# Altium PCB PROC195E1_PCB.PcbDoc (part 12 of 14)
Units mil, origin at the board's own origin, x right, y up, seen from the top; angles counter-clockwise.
Board outline 3110.24 x 2500 mil, 10 copper layers (Top Layer, L02_GND1, L03_SIG1, L04_GND2, L05_PWR1, L06_PWR2, L07_GND3, L08_SIG2, L09_GND4, Bottom Layer), stack 66.407 mil thick; 571 components, 538 nets, 6726 pads, 1286 vias.
Unrouted connection lines stored in the file: 4.
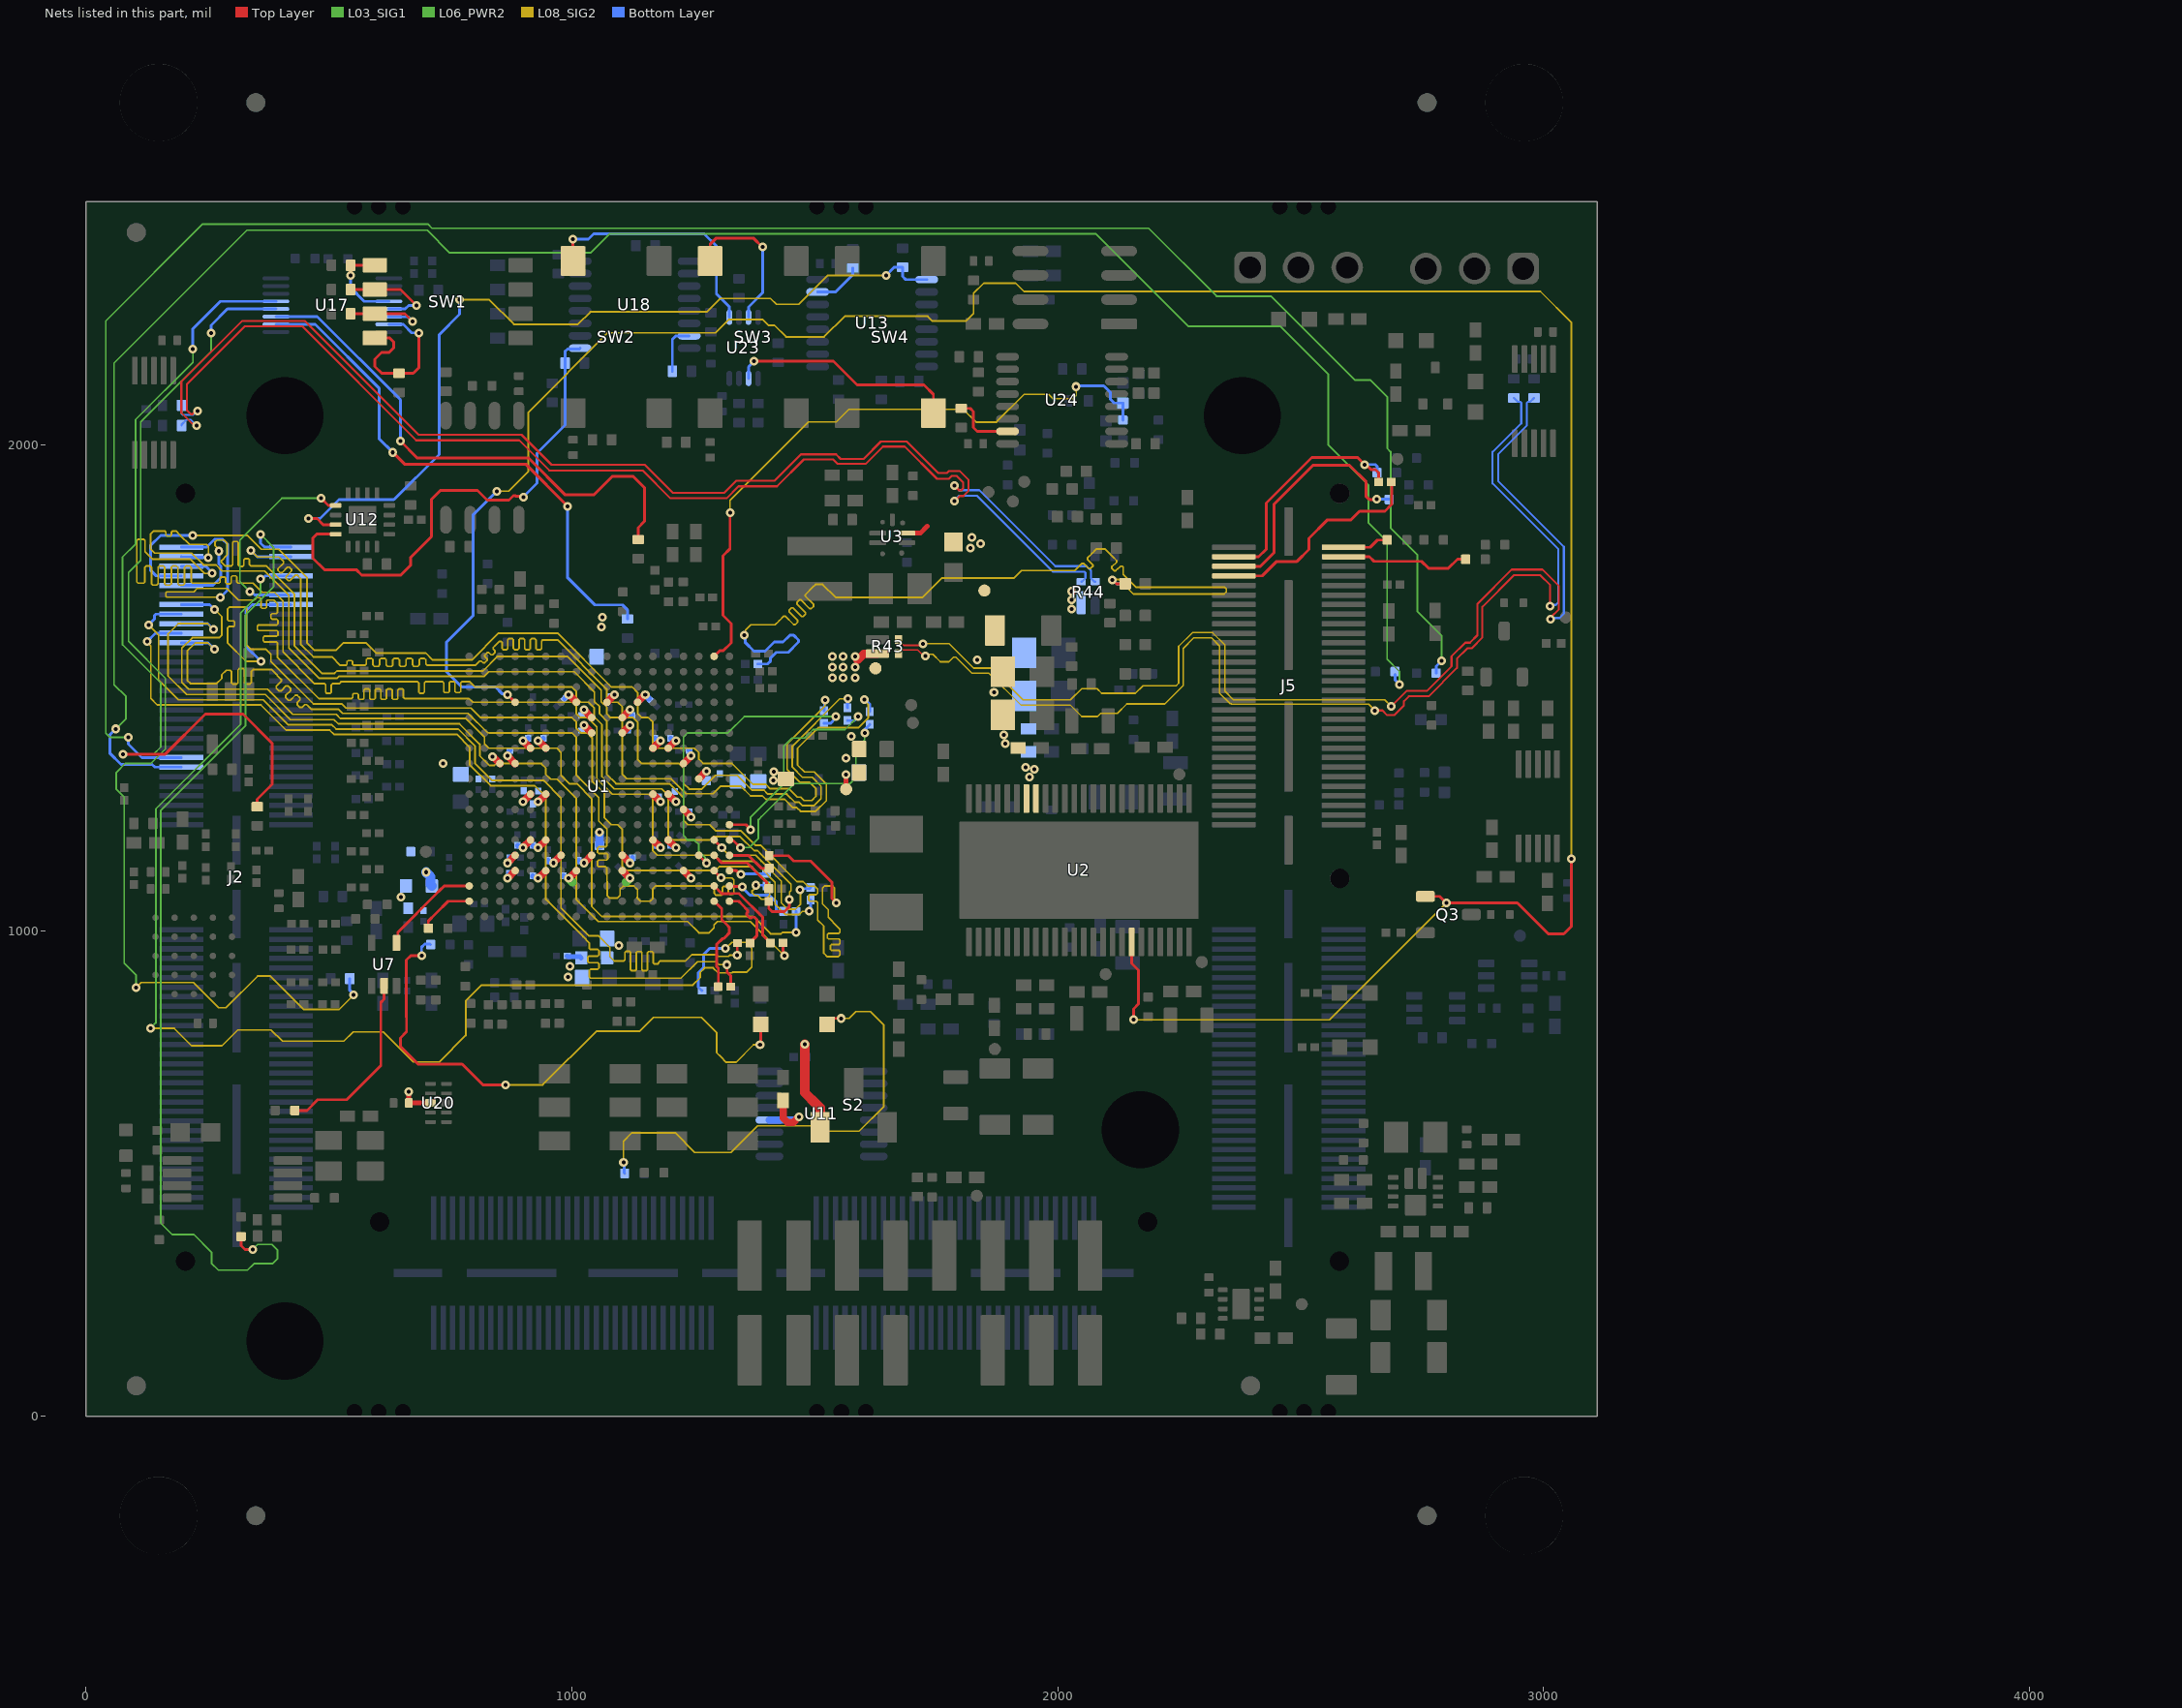
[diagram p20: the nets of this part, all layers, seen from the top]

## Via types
v1: diameter 18, hole 8, Top Layer to Bottom Layer, tented both sides, 1226 vias
v2: diameter 19.68, hole 7.87, Top Layer to Bottom Layer, tented top, 54 vias
v3: diameter 19.68, hole 7.87, Top Layer to Bottom Layer, 4 vias
v4: diameter 19.68, hole 7.87, Top Layer to Bottom Layer, tented both sides, 2 vias

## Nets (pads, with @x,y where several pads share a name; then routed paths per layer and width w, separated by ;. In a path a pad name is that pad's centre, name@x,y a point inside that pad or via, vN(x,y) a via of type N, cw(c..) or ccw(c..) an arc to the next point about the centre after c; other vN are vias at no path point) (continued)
R_PR0_PRU1_GPIO15: R91.2 R170.2 U1.A17 | length 1356.7
  Top Layer w5.66: 1311.87,1575.88 1328.05,1592.05
  Top Layer w5.8: U1.A17@1293.1,1564.41 1304.57,1575.88 1311.87,1575.88 ; v1(1325.82,1860.38) 1325.82,1786.1 1311.32,1771.6 1311.32,1649.01 1328.05,1632.27 1328.05,1629.65 1328.05,1592.05
  L08_SIG2 w3.6: v1(1325.82,1860.38) 1325.82,1885.82 1486.9,2046.9 1544.45,2046.9 1570.37,2072.82 1805.61,2072.82 1831.8,2046.63 1874.14,2046.63 1931.15,2103.63 1981.6,2103.63 1990.34,2094.89 2031.43,2094.89 2038.1,2101.55 v1(2038.1,2119.74)
  Bottom Layer w5.8: v1(2038.1,2119.74) 2039.76,2121.41 2094.91,2121.41 2108.52,2107.79 2108.52,2093.83 2116.52,2085.84 R91.2@2134.23,2085.84 R170.2@2134.23,2050.7
R_PR0_PRU1_GPIO16: R90.2 R145.1 R171.2 | length 1936.7
  Top Layer w5.8: v1(2112.5,1722.11) 2113.35,1722.11 2121.54,1713.93 R90.2@2139.12,1713.93
  L08_SIG2 w3.6: v1(1355.2,1608.12) 1357.8,1610.73 1357.8,1618.68 1368.48,1629.36 1390.29,1629.36 1418.57,1629.36 1426.89,1637.67 1436.36,1647.15 1439.64,1647.15 1456.76,1630.03 1460.04,1630.03 1464.96,1634.96 1464.96,1638.24 1447.21,1655.99 1447.21,1659.27 1452.13,1664.19 1455.41,1664.19 1473.16,1646.44 1476.44,1646.44 1481.37,1651.36 1481.37,1654.64 1463.61,1672.4 1463.61,1675.68 1468.53,1680.6 1471.81,1680.6 1489.57,1662.84 1492.85,1662.84 1497.77,1667.77 1497.77,1671.05 1480.65,1688.16 1480.65,1691.44 1496.11,1706.9 1501.74,1712.53 1516.47,1712.53 1543,1686 1722.14,1686 1761.9,1725.76 1910.79,1725.76 1926.02,1740.99 2035.21,1740.99 2040.54,1746.33 2050.02,1755.8 2053.3,1755.8 2064.16,1744.94 2067.44,1744.94 2072.36,1749.86 2072.36,1753.14 2061.5,1764.01 2061.5,1767.29 2070.61,1776.39 2079.43,1785.22 2097.78,1785.22 2112.01,1770.99 2113.28,1769.72 2121.49,1761.51 2121.34,1758.23 2111.55,1749.32 2111.39,1746.04 2116.08,1740.89 2119.35,1740.74 2129.71,1750.17 2132.99,1750.01 2135,1748 2135,1743.96 2135,1733.06 2141.51,1726.55 2161.06,1707 2343,1707 2347,1703 2347,1697.15 2342.62,1692.77 2156.14,1692.77 2126.54,1722.38 2112.77,1722.38 v1(2112.5,1722.11)
  Bottom Layer w5.8: v1(1355.2,1608.12) 1357.49,1605.83 1357.49,1592.48 1375,1574.97 1390.29,1574.97 1397.97,1574.97 1417,1594 1435.07,1594 1448.8,1607.74 1457.11,1607.74 1466.86,1597.98 1466.86,1593.92 1445.57,1572.63 1420.69,1572.63 1409.32,1561.26 1409.32,1554.91 1403.11,1548.7 1390.29,1548.7 R145.1@1383.21,1548.7 ; v1(2112.5,1722.11) 2113.38,1722.11 2121.56,1713.93 R171.2@2139.61,1713.93
R_RGMII1_RD0: R264.1 R283.1 U1.U17 | length 201.8
  Top Layer w5.6: U1.U17@1293.1,1060.47 1308.87,1044.7 ; 1308.87,1022.54 1308.96,1022.44 1308.96,1022.3
  Top Layer w5.66: 1308.87,1022.54 1308.87,1044.7
  Top Layer w5.8: R264.1@1301.74,885.17 1301.85,885.28 1301.85,922.49 1298.04,926.31 1298.04,971.21 1310.59,983.76 1313.01,983.76 1316.59,987.34 1323.92,994.67 1323.92,1007.35 1318.07,1013.2 1308.96,1022.3
R_RGMII1_RD1: R284.1 R285.1 U1.T17 | length 186.2
  Top Layer w5.6: U1.T17@1293.1,1091.97 1308.81,1076.26 ; 1328.89,1076.26 1344.3,1076.26 1393.03,1027.53 1393.03,990.41 R284.1@1408.9,974.55
  Top Layer w5.66: 1308.81,1076.26 1328.89,1076.26
R_RGMII1_RD2: R286.1 R287.1 U1.U18 | length 135.2
  Top Layer w5.8: U1.U18@1324.6,1060.47 1343.55,1060.47 1349.97,1054.05 1361.78,1042.24 1361.78,1037.43 1360.47,1036.13 1360.47,1032.23 1366.33,1026.37 1370.23,1026.37 1371.54,1027.68 1376.34,1027.68 1380.01,1024.01 1380.69,1023.32 1380.69,988.86 1366.8,974.96 R286.1@1366.8,974.18
R_RGMII1_RD3: R288.1 R289.1 U1.T18 | length 143.7
  Top Layer w5.8: U1.T18@1324.6,1091.97 1325.6,1090.97 1350.52,1090.97 v1(1351.52,1089.97)
  Bottom Layer w5.8: v1(1351.52,1089.97) 1351.52,1088.19 1366.69,1073.02 1390.29,1073.02 1406.94,1073.02 1420.5,1059.46 1420.5,1042.55 1423.37,1039.68 1435.52,1039.68 R288.1@1435.67,1039.53
R_RGMII1_RX_CTL: R290.1 R291.1 U1.R18 | length 80.4
  Top Layer w5.8: U1.R18@1324.6,1123.46 1338.57,1123.46 1346,1116.03 v1(1348.05,1116.03)
  Bottom Layer w5.8: v1(1348.05,1116.03) 1349.07,1117.04 1390.29,1117.04 1400.06,1117.04 R290.1@1401.07,1118.06
R_RGMII1_TD0: R6.1 U1.P16 | length 671.3
  Top Layer w5.8: U1.P16@1261.61,1154.96 v1(1277.35,1139.21)
  L03_SIG1 w3.6: v1(1277.35,1139.21) 1274.6,1141.96 1274.6,1150.02 1261.75,1162.86 1261.75,1177.01 1252.36,1186.41 1239.45,1186.41 1230.06,1195.79 1230.06,1233.75 1230.06,1321.68 1230.06,1398.47 1238.56,1406.97 1321.61,1406.97 1355.35,1440.72 1542.98,1440.72 v1(1543.24,1440.46)
  Bottom Layer w5.8: R6.1@1519.07,1426.82 1533.1,1426.82 1536.5,1430.22 1536.5,1430.67 1543.24,1437.42 v1(1543.24,1440.46)
R_RGMII1_TD1: R292.1 R293.1 U1.P17 | length 145.8
  Top Layer w5.6: U1.P17@1293.1,1154.96 1308.91,1139.15 ; 1361.23,1139.15 1390.29,1110.09
  Top Layer w5.66: 1308.91,1139.15 1318.07,1139.15 ; 1318.09,1139.17 1331.1,1139.17 1361.23,1139.15
  Top Layer w5.8: 1390.29,1110.09 1400.94,1099.44 1400.94,1090.91 R292.1@1405.5,1086.35
R_RGMII1_TD2: R294.1 R295.1 U1.P18 | length 93
  Top Layer w5.66: U1.P18@1324.6,1154.96 1363.74,1154.96
  Top Layer w5.8: 1363.74,1154.96 1390.52,1128.18 R294.1@1406.47,1128.18
R_RGMII1_TD3: R296.1 R297.1 U1.N17 | length 322.1
  Top Layer w5.8: U1.N17@1293.1,1186.45 v1(1308.8,1170.75)
  L08_SIG2 w3.6: v1@1308.51,1170.71 1308.51,1170.42 1323.88,1155.05 1378.21,1155.05 1390.29,1142.97 1431.37,1101.89 1431.37,1057.06 1444.44,1043.99 1460.04,1043.99 1470.97,1054.92 1470.97,1082.53 v1(1469.4,1084.1)
  Bottom Layer w5.8: v1(1469.4,1084.1) 1471.65,1086.35 1489.36,1086.35 R296.1@1491.61,1088.61
R_RGMII1_TX_CTL: R7.1 U1.M18 | length 452.1
  Top Layer w5.8: U1.M18@1324.6,1217.95 1358.56,1217.95 1368.34,1208.16 v1(1368.34,1207.41)
  L03_SIG1 w3.6: v1(1368.34,1207.41) 1368.34,1233.69 1390.29,1255.64 1436.48,1301.83 1436.48,1379.46 1453.41,1396.39 1479.35,1396.39 1496.65,1413.7 1562.41,1413.7 v1@1588.94,1440.23
  Bottom Layer w5.8: R7.1@1567.51,1432.71 1568,1432.21 1581.57,1432.21 1588.94,1439.59 v1(1588.94,1440.56)
R_RGMII1_TXC: R238.1 U1.N18 | length 470.8
  Top Layer w5.8: U1.N18@1324.6,1186.45 1326.53,1184.52 1333.18,1184.52 v1(1346.75,1170.95)
  L03_SIG1 w3.6: v1(1346.75,1170.95) 1365.55,1170.95 1384.23,1189.64 1384.23,1228.29 1390.29,1234.35 1458.55,1302.61 1573.17,1302.61 1584.95,1314.39 1584.95,1375.05 1602.8,1392.9 v1(1602.8,1406.53)
  Bottom Layer w5.8: v1(1602.8,1406.53) 1603.56,1407.3 1603.56,1414.23 1613.18,1423.85 R238.1@1613.18,1424.63
RES0_PWMOUT0: J2.48 R8.2 | length 4476.4
  L03_SIG1 w3.6: v1(62,1415.22) 82.78,1435.99 82.78,1446.52 82.64,1446.66 82.64,1460.58 82.78,1460.72 82.78,1481.69 58.4,1506.07 58.4,2168.04 331.79,2441.44 702.62,2441.44 749.06,2395 1038.99,2395 1078.31,2434.32 2078.3,2434.32 2269.09,2243.53 2458.69,2243.53 2556.78,2145.44 2556.78,2000.22 2639.34,1917.66 2639.34,1839.52 2678.06,1800.8 2678.06,1558.68 2703.43,1533.31 v1(2703.43,1506.69)
  Bottom Layer w5.8: v1(62,1415.22) 49.37,1402.58 49.37,1365.47 72.94,1341.9 136.73,1341.9 142.16,1336.48 J2.48@196.81,1336.48 ; R8.2@2694.51,1527.01 2694.51,1515.73 2703.43,1506.81 v1(2703.43,1506.69)
RES0_PWMOUT1: J2.46 R5.2 | length 4519.7
  L03_SIG1 w3.6: v1(87.73,1397.66) 49.95,1397.66 41.19,1406.42 41.19,2254.72 240.68,2454.22 703.74,2454.22 712.38,2445.57 2187.18,2445.57 2326.97,2305.79 2439.21,2305.79 2612,2133 2643.83,2133 2678.17,2098.66 2678.17,1992.65 2685.29,1985.52 2685.29,1828.54 2740.48,1773.36 2740.48,1656.77 2790.3,1606.95 v1(2790.3,1555.56)
  Bottom Layer w5.8: v1(87.73,1397.66) 87.73,1383.91 115.48,1356.16 J2.46@196.81,1356.16 ; R5.2@2778.9,1529.81 2778.9,1544.16 v1(2790.3,1555.56)
RGMII1_ETH1_CLK: J2.1 R3.2 | length 2035.4
  Top Layer w5.8: R3.2@319.67,370.21 319.67,351.8 327.85,343.61 343.15,343.61 v1(343.28,343.49)
  L03_SIG1 w3.6: v1(343.28,343.49) 353.65,353.87 383.02,353.87 394.62,342.27 394.62,324.88 384.17,314.43 346.21,314.43 332.79,301 272.94,301 258.88,315.05 258.88,337.89 222.31,374.45 178.02,374.45 154.1,398.38 154.1,1246.67 328.49,1421.06 328.49,1649.63 386.29,1707.43 386.29,1788.9 v1(359.82,1815.37)
  Bottom Layer w5.8: v1(359.82,1815.37) 359.82,1797.59 368.18,1789.23 J2.1@422.41,1789.23
RGMII1_INTn: J2.7 R79.1 | length 2765.5
  L03_SIG1 w3.6: v1(133,799) 144.12,810.12 144.12,1250.28 318.89,1425.04 318.89,1654.03 359.78,1694.92 v1(359.78,1723.2)
  L08_SIG2 w3.6: v1(133,799) 182,799 218,763 280.32,763 312.89,795.57 381.38,795.57 404.61,772.35 531,772.35 550.26,791.61 612.11,791.61 673.86,729.86 727.65,729.86 782.05,784.26 782.05,855.17 814.64,887.76 1249.26,887.76 1264.39,902.88 1264.39,914 1273.58,923.2 1291.25,923.2 1301.3,913.14 1330.11,913.14 1331.67,914.7 1360.48,914.7 1370.42,924.64 1370.42,963.3 1358.09,975.63 1329.38,975.63 1317.29,963.54 v1(1315.94,963.54)
  Bottom Layer w5.8: v1(359.78,1723.2) 362.77,1723.2 369.75,1730.18 J2.7@422.41,1730.18 ; R79.1@1268.44,876.51 1267.65,876.51 1260.43,883.74 1260.43,913.02 1271.46,924.05 1271.46,950.96 1284.04,963.54 v1(1315.94,963.54)
RGMII1_RD0: J2.20 R264.2 | length 1946.7
  Top Layer w5.8: v1(1319.72,929.94) 1319.72,914.77 1327.33,907.15 R264.2@1327.33,884.78
  L08_SIG2 w3.6: v1(126.13,1594.78) 126.13,1593.3 133.96,1585.47 133.96,1477.82 147.41,1464.37 360.66,1464.37 412.34,1412.69 502.01,1412.69 510.63,1404.07 720.46,1404.07 763.43,1404.07 790.04,1377.45 790.04,1341.46 833.09,1298.41 923.69,1298.41 946.69,1275.4 946.69,1170.66 946.69,1064.12 1023.47,987.34 1036.14,974.68 1036.14,969.31 1036.14,963.95 1038.86,961.23 1053.42,961.23 1056.14,958.51 1056.14,950.35 1053.42,947.63 1035.69,947.63 1032.97,944.91 1032.97,936.75 1035.69,934.03 1053.42,934.03 1056.14,931.31 1056.14,923.15 1053.42,920.43 1038.86,920.43 1036.14,917.71 1036.14,904.75 1038.58,902.31 1038.89,902 1224.61,902 1258.73,936.13 1296.49,936.13 1302.68,929.94 v1(1319.72,929.94)
  Bottom Layer w5.8: v1(126.13,1594.78) 143.41,1612.07 J2.20@196.81,1612.07
RGMII1_RD1: J2.18 R284.2 | length 1969
  Top Layer w5.8: R284.2@1434.88,974.55 1434.88,954.26 1437.8,951.34 v1(1437.8,948.04)
  L08_SIG2 w3.6: v1(262.85,1619.96) 250.97,1631.84 190.3,1631.84 169.27,1610.81 169.27,1524.1 207.4,1485.97 369.61,1485.97 421.29,1434.29 510.95,1434.29 519.57,1425.67 720.46,1425.67 768.98,1425.67 810.91,1383.73 810.91,1359.92 821.79,1349.05 830.81,1340.02 840.79,1340.02 844.66,1343.89 937.4,1343.89 946.64,1334.64 946.64,1321.73 956.94,1311.44 969.81,1311.44 1009.59,1271.65 1009.59,1063.57 1054.64,1018.52 1205.65,1018.52 1205.71,1018.57 1238.57,1018.57 1261.77,995.37 1282.9,995.37 1292.92,1005.39 1292.92,1011.34 1300.09,1018.52 1367.32,1018.52 1390.29,995.55 v1(1437.8,948.04)
  Bottom Layer w5.8: J2.18@196.81,1631.75 251.06,1631.75 v1(262.85,1619.96)
RGMII1_RD2: J2.16 R286.2 | length 2021.8
  Top Layer w5.8: v1(1340.66,949.6) 1340.66,974.02 R286.2@1340.82,974.18
  L08_SIG2 w3.6: v1(129.35,1629.3) 149.88,1608.77 149.88,1515.92 190.63,1475.17 365.13,1475.17 416.82,1423.49 506.48,1423.49 515.1,1414.87 766.2,1414.87 800.95,1380.12 800.95,1344.13 835.87,1309.21 941.76,1309.21 978.09,1272.88 978.09,1101.21 977.88,1101 977.88,1082.93 978.09,1082.72 978.09,1069.71 977.88,1069.5 977.88,1046.51 1034.91,989.47 1054.53,989.47 1056.66,987.34 1078.63,965.37 1078.63,946.36 1087.59,937.4 1105.51,937.4 1107.31,937.4 1109.63,939.72 1109.63,955.08 1111.95,957.4 1118.91,957.4 1121.23,955.08 1121.23,919.72 1123.55,917.4 1130.51,917.4 1132.83,919.72 1132.83,954.47 1135.15,956.79 1142.11,956.79 1144.43,954.47 1144.43,919.72 1146.75,917.4 1153.71,917.4 1156.03,919.72 1156.03,954.47 1158.35,956.79 1165.31,956.79 1167.63,954.47 1167.63,933.6 1169.95,931.28 1176.91,931.28 1179.23,933.6 1179.23,935.08 1181.55,937.4 1201,937.4 1233.92,937.4 1246.84,950.32 1297.44,950.32 1301.02,946.74 1322.9,946.74 1325.76,949.6 v1(1340.66,949.6)
  Bottom Layer w5.8: v1(129.35,1629.3) 141.1,1641.04 141.1,1648.04 144.49,1651.44 J2.16@196.81,1651.44
RGMII1_RD3: J2.14 R288.2 | length 1983.3
  L08_SIG2 w3.6: v1(265.22,1660.81) 280.02,1646 280.02,1608.7 274.26,1602.94 219.4,1602.94 197.85,1581.4 197.85,1510.79 211.87,1496.77 374.08,1496.77 425.76,1445.09 515.43,1445.09 524.05,1436.47 720.46,1436.47 782.47,1436.47 820.51,1398.43 820.51,1384.64 829.87,1375.28 969.6,1375.28 978.15,1366.72 978.15,1337.71 978.15,1319.41 995.33,1302.23 1010.61,1302.23 1041.09,1271.75 1041.09,1049.99 1062,1029.08 1113.6,1029.08 ; 1113.62,1029.06 1126.54,1029.06 ; 1126.56,1029.08 1373.5,1029.08 1390.29,1012.29 1409.19,993.39 1430.64,993.39 1433.54,996.29 v1(1461.65,996.29)
  Bottom Layer w5.8: J2.14@196.81,1671.12 254.9,1671.12 v1(265.22,1660.81) ; v1(1461.65,996.29) R288.2@1461.65,1039.53
RGMII1_RST: J2.11 U12.5 | length 440.8
  Top Layer w5.8: v1(484.58,1889.77) 499.21,1875.13 514.32,1875.13 U12.5@514.43,1875.02
  L03_SIG1 w3.6: v1(337.55,1697.91) 317.3,1718.16 317.3,1803.62 403.46,1889.77 v1(484.58,1889.77)
  Bottom Layer w5.8: v1(337.55,1697.91) 340.85,1697.91 347.95,1690.81 J2.11@422.41,1690.81
RGMII1_RX_CTL: J2.13 R290.2 | length 2047.6
  L08_SIG2 w3.6: v1(360.46,1554.22) 329.78,1554.22 292.14,1591.86 292.14,1610 292.14,1623.4 294.46,1625.72 304.03,1625.72 306.35,1628.04 306.35,1635 304.03,1637.32 294.46,1637.32 292.14,1639.64 292.14,1647.96 292.14,1662.18 295.76,1665.8 328.65,1665.8 331.44,1663.01 331.44,1648.52 331.44,1640 331.44,1587.56 340,1579 371,1579 381.09,1568.91 381.09,1553.84 468.24,1466.69 526.6,1466.69 535.23,1458.07 792.87,1458.07 812.57,1438.37 1000.39,1438.37 1009.64,1429.13 1009.64,1416.22 1018.88,1406.97 1021,1406.97 1021.1,1406.88 1031.89,1406.88 1042.07,1396.7 1042.07,1307.52 1067.44,1282.15 1067.44,1232.14 1081.59,1218 1094.59,1218 1103.89,1208.7 1103.89,1206.77 1104.17,1206.49 1104.17,1132.71 1113.37,1123.51 1295.77,1123.51 1303.99,1131.73 1370.98,1131.73 1407.42,1095.29 1407.42,1072.19 1399.79,1064.56 1390.71,1064.56 1382.65,1072.63 1376.4,1072.63 1371.17,1077.85 1371.17,1081.74 1378.91,1089.48 v1(1378.91,1093.38)
  Bottom Layer w5.8: v1(360.46,1554.22) 330.03,1584.65 330.03,1658.59 342.56,1671.12 J2.13@422.41,1671.12 ; v1(1378.91,1093.38) 1399.77,1093.38 R290.2@1401.07,1092.07
RGMII1_RXC: J2.22 U1.R17 | length 2146.7
  Top Layer w5.8: U1.R17@1293.1,1123.46 1293.1,1122.92 1307.55,1108.48 v1(1307.55,1108.39)
  L08_SIG2 w3.6: v1(264.72,1578.82) 251.37,1592.17 225.76,1592.17 209.11,1575.52 209.11,1514.8 215.36,1508.55 269.55,1508.55 280,1519 280,1526.57 289.24,1535.81 296.96,1535.81 299.68,1533.09 299.68,1510.29 302.4,1507.57 310.56,1507.57 313.28,1510.29 313.28,1536.36 316,1539.08 324.16,1539.08 326.88,1536.36 326.88,1510.29 329.6,1507.57 337.76,1507.57 340.48,1510.29 340.48,1533.09 343.2,1535.81 343.58,1536.18 344.81,1537.42 382.11,1537.42 384.77,1534.77 386.04,1533.49 402.42,1517.11 402.42,1513.26 392.13,1502.96 392.13,1499.12 397.9,1493.35 401.75,1493.35 412.1,1503.71 415.95,1503.71 421.72,1497.94 421.72,1494.09 411.36,1483.73 411.36,1479.88 417.13,1474.11 420.98,1474.11 431.34,1484.47 435.18,1484.47 440.95,1478.7 440.95,1474.86 435.13,1469.03 435.13,1465.19 440.9,1459.42 444.75,1459.42 450.51,1465.18 454.35,1465.18 455.63,1463.9 463.64,1455.89 519.9,1455.89 528.52,1447.27 720.46,1447.27 786.95,1447.27 827.05,1407.16 829.72,1407.16 830,1406.88 1000.39,1406.88 1009.59,1397.68 1009.59,1319.82 1055.78,1273.63 1055.78,1225.41 1072.49,1208.7 1072.49,1186.6 1072.38,1186.49 1072.38,1175.08 1069.66,1172.36 1055.69,1172.36 1052.97,1169.64 1052.97,1161.48 1055.69,1158.76 1071.53,1158.76 1074.25,1156.04 1074.25,1147.88 1071.53,1145.16 1055.69,1145.16 1052.97,1142.44 1052.97,1134.28 1055.69,1131.56 1069.66,1131.56 1072.38,1128.84 1072.38,1127.04 1072.38,1114.99 1072.58,1114.78 1072.58,1101.31 1073.26,1100.63 1073.26,1071.52 1077.64,1067.13 1094.34,1067.13 1099.67,1072.46 1099.67,1085.22 1106.32,1091.86 1127.97,1091.86 1135.43,1084.41 1135.43,1069.8 1135.19,1069.57 1135.19,1066.59 1141.19,1060.59 1161.59,1060.59 1167,1066 1167,1069.65 1167.07,1069.71 1167.07,1082.72 1167,1082.79 1167,1086.27 1172.68,1091.95 1290.74,1091.95 1293.64,1089.05 1293.64,1076.36 1297.2,1072.8 1307.77,1072.8 1310,1075.03 1310,1088.77 1312.23,1091 1319,1091 1321.97,1088.03 1321.97,1078.03 1325.63,1074.37 1331.51,1074.37 1333.74,1076.6 1333.74,1104.76 1330.1,1108.39 v1(1307.55,1108.39)
  Bottom Layer w5.8: J2.22@196.81,1592.38 252.07,1592.38 264.72,1579.73 v1(264.72,1578.82)
RGMII1_TD0: J2.8 R6.2 | length 2210.5
  L08_SIG2 w3.6: v1(220.46,1813.61) 332.56,1813.61 361.4,1784.77 397.26,1784.77 455.23,1726.8 455.23,1592.94 471.17,1577.01 515.03,1577.01 529.96,1591.94 577.06,1591.94 597.67,1571.33 699.52,1571.33 713.71,1557.15 720.46,1557.15 794.74,1557.15 849.73,1612.14 970.78,1612.14 1081.45,1501.46 1124.27,1501.46 1135.67,1490.07 1135.67,1446.97 1144.22,1438.42 1157.53,1438.42 1157.68,1438.27 1157.83,1438.27 1166.97,1429.14 1166.97,1428.98 1167.07,1428.88 1167.07,1397.68 1167.07,1385.04 1167.27,1384.84 1167.27,1384.72 1176.4,1375.58 1176.53,1375.58 1176.83,1375.28 1252.32,1375.28 1261.46,1366.14 1261.46,1353.21 1270.68,1343.98 1329.82,1343.98 1372.69,1301.11 1390.29,1301.11 1399.13,1301.11 1408.35,1291.88 1447.21,1291.88 1464.28,1274.81 1470.85,1274.81 1477.87,1267.79 1493.91,1267.79 1502.41,1276.29 1502.41,1292.74 1490.26,1304.9 1470.18,1304.9 1443.2,1331.87 1443.2,1384.13 1521.1,1462.03 v1(1521.1,1474.32)
  Bottom Layer w5.8: J2.8@196.81,1730.18 145.1,1730.18 133.15,1742.12 133.15,1792.37 154.38,1813.61 v1(220.46,1813.61) ; R6.2@1519.07,1452.8 1520.09,1453.82 1520.09,1473.3 v1(1521.1,1474.32)
RGMII1_TD1: J2.6 R292.2 | length 2752.3
  Top Layer w5.8: R292.2@1405.5,1060.37 1405.5,1046.03 1412.29,1039.24 1437.72,1039.24 1448.17,1049.69 v1(1448.17,1064.02)
  L08_SIG2 w3.6: v1(260.11,1735.29) 244.43,1735.29 215.51,1764.21 137.79,1764.21 121.84,1780.16 121.84,1803.2 119.74,1805.31 107.29,1805.31 105.19,1803.2 105.19,1717.73 107.91,1715 116.43,1715 118.96,1715 121.68,1717.72 121.68,1747.7 124.4,1750.42 132.56,1750.42 135.28,1747.7 135.28,1713.93 138,1711.21 146.16,1711.21 148.88,1713.93 148.88,1747.7 151.6,1750.42 159.76,1750.42 162.48,1747.7 162.48,1713.93 165.2,1711.21 173.36,1711.21 176.08,1713.93 176.08,1747.7 178.8,1750.42 186.96,1750.42 189.68,1747.7 189.68,1713.93 192.4,1711.21 200.56,1711.21 203.28,1713.93 203.28,1747.7 206,1750.42 214.16,1750.42 216.88,1747.7 216.88,1717.72 219.6,1715 235,1715 272.21,1715 274.01,1715 276.33,1717.32 276.33,1725.43 278.65,1727.75 285.61,1727.75 287.93,1725.43 287.93,1716.12 290.25,1713.8 297.21,1713.8 299.53,1716.12 299.53,1727.64 301.85,1729.96 308.81,1729.96 311.13,1727.64 311.13,1717.32 313.45,1715 317.69,1715 344.22,1715 363.02,1696.2 388.49,1696.2 406.02,1678.67 406.02,1573.42 471.15,1508.29 478.03,1508.29 491.43,1508.29 493.75,1505.97 493.75,1490.61 496.07,1488.29 503.03,1488.29 505.35,1490.61 505.35,1505.97 507.67,1508.29 519.23,1508.29 521.24,1508.29 525.24,1512.28 669.5,1512.28 682.9,1512.28 685.22,1509.96 685.22,1491.01 687.54,1488.69 694.5,1488.69 696.82,1491.01 696.82,1509.96 699.14,1512.28 720,1512.28 721,1512.28 734.4,1512.28 736.72,1509.96 736.72,1492.21 739.04,1489.89 746,1489.89 748.32,1492.21 748.32,1510.37 750.64,1512.69 757.6,1512.69 759.92,1510.37 759.92,1492.21 762.24,1489.89 769.2,1489.89 771.52,1492.21 771.52,1509.96 773.84,1512.28 780.83,1512.28 790.65,1512.28 801.68,1501.25 829.78,1501.25 829.91,1501.37 1000.39,1501.37 1009.64,1492.12 1009.64,1479.21 1018.88,1469.97 1021,1469.97 1021.1,1469.87 1034.74,1469.87 1046.48,1458.13 1046.48,1439.7 1062.17,1424.01 1062.17,1317.14 1087.58,1291.74 1184.85,1291.74 1198.66,1277.93 1198.66,1195.7 1207.86,1186.5 1283.86,1186.5 1290.77,1193.42 1346.7,1193.42 1375.47,1164.65 1382.19,1164.65 1390.29,1156.54 1451.43,1095.4 1451.43,1082.65 1448.17,1079.38 v1(1448.17,1064.02)
  Bottom Layer w5.8: J2.6@196.81,1749.86 246.84,1749.86 260.11,1736.59 v1(260.11,1735.29)
RGMII1_TD2: J2.4 R294.2 | length 2808
  Top Layer w5.8: R294.2@1406.47,1154.16 1446.05,1154.16 1456.92,1143.29 1491.73,1143.29 1535.45,1099.57 1535.45,1066.18 1544.87,1056.77 v1(1544.87,1056.69)
  L08_SIG2 w3.6: v1(252.42,1767.87) 252.42,1790.88 248.3,1795 213.29,1795 195.06,1813.23 185.84,1822.45 178.92,1822.45 176.6,1820.13 176.6,1814.29 174.28,1811.97 167.32,1811.97 165,1814.29 165,1820.13 162.68,1822.45 149.28,1822.45 139.59,1822.45 133.27,1816.13 133.27,1785.73 142,1777 218,1777 242.35,1752.65 267.94,1752.65 280.6,1740 368.16,1740 418,1690.16 418,1581.9 480.82,1519.09 516.77,1519.09 521.18,1523.49 820.36,1523.49 828.86,1532 829.04,1532 829.91,1532.86 1005.32,1532.86 1046.8,1491.38 1046.8,1471.38 1057.28,1460.91 1057.28,1446.44 1072.16,1431.56 1072.16,1321.47 1091.25,1302.38 1201.04,1302.38 1230.06,1273.35 1230.06,1258.79 1230.16,1258.69 1230.16,1227.19 1238.35,1219 1239.35,1218 1283.76,1218 1296.46,1205.29 1348.4,1205.29 1377.9,1175.79 1388.6,1175.79 1463.49,1100.9 1476.36,1100.9 1485.82,1091.44 1499.75,1091.44 1506,1085.18 1506,1076.94 1503.28,1074.22 1490.1,1074.22 1487.38,1071.5 1487.38,1063.34 1490.1,1060.62 1503.28,1060.62 1506,1057.9 1506,1056.1 1506,1022 1518.6,1009.4 1518.6,953.46 1525.91,946.15 1548.24,946.15 1552.1,950.01 1552.1,953.31 1552.1,957.22 1549.78,959.54 1534.61,959.54 1532.29,961.86 1532.29,968.82 1534.61,971.14 1549.78,971.14 1552.1,973.46 1552.1,980.42 1549.78,982.74 1528.52,982.74 1526.2,985.06 1526.2,992.02 1528.52,994.34 1549.78,994.34 1552.1,996.66 1552.1,1003.01 1547.37,1007.74 1527.88,1027.23 1527.88,1043.12 1516,1055 1516,1087.53 1520.53,1092.06 1536.62,1092.06 1540.33,1088.36 1540.33,1065.12 1544.87,1060.58 v1(1544.87,1056.69)
  Bottom Layer w5.8: J2.4@196.81,1769.55 197.65,1768.71 251.59,1768.71 v1(252.42,1767.87)
RGMII1_TD3: J2.2 R296.2 | length 2554.3
  L08_SIG2 w3.6: v1(276.82,1685.98) 276.54,1686.25 167.14,1686.25 164.91,1688.48 164.91,1695.02 167.14,1697.25 222.22,1697.25 229.18,1704.2 290.34,1704.2 314.32,1680.22 321.48,1680.22 346.48,1680.22 348.8,1682.54 348.8,1683.09 351.12,1685.41 358.08,1685.41 360.4,1683.09 360.4,1665.64 362.72,1663.32 369.68,1663.32 372,1665.64 372,1677.9 374.32,1680.22 383.53,1680.22 386.87,1680.22 394.29,1672.8 394.29,1668.13 394.29,1654.73 391.97,1652.41 383.53,1652.41 381.21,1650.09 381.21,1643.13 383.53,1640.81 393.17,1640.81 395.49,1638.49 395.49,1631.53 393.17,1629.21 355.43,1629.21 353.11,1626.89 353.11,1619.93 355.43,1617.61 393.17,1617.61 395.49,1615.29 395.49,1608.33 393.17,1606.01 367.56,1606.01 365.24,1603.69 365.24,1596.73 367.56,1594.41 391.97,1594.41 394.29,1592.09 394.29,1567.34 394.29,1563 479.8,1477.49 542.01,1477.49 547.05,1477.49 549.37,1479.81 549.37,1485.69 551.69,1488.01 558.65,1488.01 560.97,1485.69 560.97,1478.29 563.29,1475.97 570.25,1475.97 572.57,1478.29 572.57,1495.17 574.89,1497.49 581.85,1497.49 584.17,1495.17 584.17,1478.29 586.49,1475.97 593.45,1475.97 595.77,1478.29 595.77,1495.17 598.09,1497.49 605.05,1497.49 607.37,1495.17 607.37,1478.29 609.69,1475.97 616.65,1475.97 618.97,1478.29 618.97,1495.17 621.29,1497.49 628.25,1497.49 630.57,1495.17 630.57,1478.29 632.89,1475.97 639.85,1475.97 642.17,1478.29 642.17,1495.17 644.49,1497.49 651.45,1497.49 653.77,1495.17 653.77,1479.81 656.09,1477.49 669.5,1477.49 788.73,1477.49 796.34,1469.87 1000.39,1469.87 1009.59,1460.67 1009.59,1458.55 1009.64,1458.5 1009.64,1446.17 1017.43,1438.37 1031.89,1438.37 1032.19,1438.07 1032.66,1438.07 1051.67,1419.06 1051.67,1313.01 1083.79,1280.89 1157.87,1280.89 1167.07,1271.7 1167.07,1164.3 1176.36,1155.01 1294.58,1155.01 1306.9,1142.68 1375.3,1142.68 1390.29,1127.69 1418.24,1099.74 1418.24,1054.71 1439.76,1033.19 1468.18,1033.19 1474.68,1039.7 v1(1488.99,1039.7)
  Bottom Layer w5.8: J2.2@196.81,1789.23 248.92,1789.23 265.03,1805.35 281.45,1805.35 291.64,1795.16 291.64,1700.8 v1(276.82,1685.98) ; v1(1488.99,1039.7) 1488.99,1043 1491.61,1045.62 R296.2@1491.61,1062.62
RGMII1_TX_CTL: J2.3 R7.2 | length 2423.6
  L08_SIG2 w3.6: v1(340.07,1782.34) 353.24,1769.17 397.58,1769.17 398.85,1767.9 407.06,1759.7 407.06,1756.42 395.46,1744.82 395.46,1741.54 400.39,1736.62 403.67,1736.62 415.26,1748.21 418.54,1748.21 423.46,1743.29 423.46,1740.01 411.87,1728.42 411.87,1725.14 416.79,1720.22 420.07,1720.22 431.66,1731.81 434.95,1731.81 442.11,1724.65 442.2,1724.56 442.2,1722.2 442.2,1589.51 468.22,1563.49 506.51,1563.49 524,1546 533.56,1546 535.36,1546 537.68,1548.32 537.68,1553.57 540,1555.89 546.96,1555.89 549.28,1553.57 549.28,1548.32 551.6,1546 566,1546 572.92,1546 574.72,1546 577.44,1548.72 577.44,1557.44 580.16,1560.16 588.32,1560.16 591.04,1557.44 591.04,1546.61 593.76,1543.89 601.92,1543.89 604.64,1546.61 604.64,1557.44 607.36,1560.16 615.52,1560.16 618.24,1557.44 618.24,1546.61 620.96,1543.89 629.12,1543.89 631.84,1546.61 631.84,1557.44 634.56,1560.16 642.72,1560.16 645.44,1557.44 645.44,1546.61 648.16,1543.89 656.32,1543.89 659.04,1546.61 659.04,1557.44 661.76,1560.16 669.92,1560.16 672.64,1557.44 672.64,1546.61 675.36,1543.89 683.52,1543.89 686.24,1546.61 686.24,1557.44 688.96,1560.16 697.12,1560.16 699.84,1557.44 699.84,1548.72 702.56,1546 719,1546 795.96,1546 801.82,1546 810.68,1554.87 813.97,1554.87 817.63,1551.2 820.91,1551.2 825.83,1556.12 825.83,1559.4 821.32,1563.92 821.32,1567.2 826.24,1572.12 829.52,1572.12 834.04,1567.61 837.32,1567.61 842.24,1572.53 842.24,1575.81 838.57,1579.47 838.57,1582.75 841.93,1586.11 843.43,1587.61 851.23,1595.41 854.51,1595.41 856.83,1593.09 856.83,1580.63 859.15,1578.31 866.11,1578.31 868.43,1580.63 868.43,1598.66 870.75,1600.98 877.71,1600.98 880.03,1598.66 880.03,1580.63 882.35,1578.31 889.31,1578.31 891.63,1580.63 891.63,1598.66 893.95,1600.98 900.91,1600.98 903.23,1598.66 903.23,1580.63 905.55,1578.31 912.51,1578.31 914.83,1580.63 914.83,1598.66 917.15,1600.98 924.11,1600.98 926.43,1598.66 926.43,1580.63 928.75,1578.31 935.71,1578.31 938.03,1580.63 938.03,1595.99 940.35,1598.31 947.44,1598.31 970.82,1598.31 1071.91,1497.22 1071.91,1479.93 1081.97,1469.87 1094.88,1469.87 1104.17,1460.58 1104.17,1447.67 1113.37,1438.47 1125.13,1438.47 1125.23,1438.37 1126.38,1438.37 1135.67,1429.08 1135.67,1353.18 ; 1135.7,1353.15 1135.7,1352.73 1144.55,1343.89 1220.86,1343.89 1230.06,1334.69 1230.06,1302.94 1241.69,1291.31 1268.08,1291.31 1296.26,1319.49 1340.73,1319.49 1370.98,1289.25 1390.29,1289.25 1395.72,1289.25 1403.88,1281.08 1442.73,1281.08 1459.81,1264.01 1467.9,1264.01 1474.81,1257.1 1498.5,1257.1 1513.21,1271.81 1513.21,1297.22 1494.73,1315.7 1474.65,1315.7 1454,1336.35 1454,1379.66 1551.5,1477.16 v1(1568,1477.16)
  Bottom Layer w5.8: v1(340.07,1782.34) 352.86,1769.55 J2.3@422.41,1769.55 ; R7.2@1567.51,1458.7 1567.75,1458.94 1567.75,1476.91 v1(1568,1477.16)
RGMII1_TXC: J2.10 R238.2 | length 2403.6
  L08_SIG2 w3.6: v1(273.74,1780.94) 273.74,1784.55 266.26,1792.03 266.26,1800.26 270.01,1804.01 284.63,1804.01 290.66,1797.97 290.66,1772.86 279.18,1761.38 279.18,1758.23 286.62,1750.8 292.51,1750.8 299.91,1750.8 302.23,1753.12 302.23,1798.69 304.55,1801.01 311.51,1801.01 313.83,1798.69 313.83,1751.92 316.15,1749.6 323.11,1749.6 325.43,1751.92 325.43,1763.22 327.75,1765.54 334.71,1765.54 337.03,1763.22 337.03,1753.12 339.35,1750.8 352.75,1750.8 370.94,1750.8 429.67,1692.07 429.67,1585.51 485.62,1529.56 511.97,1529.56 516.7,1534.29 817.58,1534.29 847.59,1564.31 892.85,1564.31 892.9,1564.36 968.9,1564.36 968.95,1564.31 991.25,1564.31 1060.72,1494.84 1060.72,1471.04 1072.12,1459.64 1072.12,1446.04 1079.69,1438.47 1096.2,1438.47 1104.13,1430.54 1104.13,1321.75 1104.17,1321.7 1113.37,1312.49 1126.38,1312.49 1126.44,1312.55 1144.8,1312.55 1144.87,1312.49 1189.37,1312.49 1189.43,1312.55 1204.44,1312.55 1235.28,1281.71 1290.71,1281.71 1306.4,1297.4 1347.93,1297.4 1368.08,1277.26 1390.29,1277.26 1392.43,1277.26 1399.41,1270.28 1438.26,1270.28 1455.34,1253.21 1463.43,1253.21 1471,1245.64 1502.31,1245.64 1524.01,1267.34 1524.01,1301.69 1499.2,1326.5 1479.13,1326.5 1464.8,1340.82 1464.8,1375.19 1507.07,1417.46 1589.96,1417.46 1610.02,1437.52 1610.02,1466.08 1602.36,1473.74 v1(1602.36,1475.39)
  Bottom Layer w5.8: J2.10@196.81,1710.49 261.99,1710.49 278.01,1726.52 278.01,1750.33 273.86,1754.48 273.86,1780.81 v1(273.74,1780.94) ; v1(1602.36,1475.39) 1604.26,1475.39 1613.18,1466.47 R238.2@1613.18,1450.62
RTCK/EXTC: J5.7 R65.2 | length 444.9
  Top Layer w5.8: J5.7@2362.59,1730.1 2420.86,1730.1 2450.68,1759.92 2492.45,1759.92 2516.94,1784.41 2516.94,1807.32 2554.48,1844.86 2602.94,1844.86 2621.27,1863.19 2673.41,1863.19 2687.06,1876.85 R65.2@2687.06,1923.06
SAFETY_ERRORn: Q3.1 U1.D4 U2.18 | length 5634.1
  Top Layer w5.8: v1(867.61,1485.67) 883.36,1469.92 U1.D4@883.65,1469.92 ; U2.18@2152.28,976.67 2152.28,932.67 2166.2,918.75 2166.2,849.13 2156.08,839.01 v1(2156.08,816.43) ; Q3.1@2756.73,1070.44 2786.29,1070.44 v1(2799.82,1056.91) 2945.86,1056.91 3009.79,992.98 3041.58,992.98 3057.23,1008.64 v1(3057.23,1147.69)
  L08_SIG2 w3.6: v1(845.85,1904.1) 846.27,1904.53 870.27,1904.53 910.93,1945.18 910.93,2067.1 1074.05,2230.21 1296.14,2230.21 1323.91,2257.99 1392.82,2257.99 1404.73,2246.07 1416.97,2246.07 1440.95,2222.1 1519.42,2222.1 1561.86,2264.54 1732.6,2264.54 1742.66,2254.48 1810.95,2254.48 1826.9,2270.44 1826.9,2311.67 1847.74,2332.5 1913.55,2332.5 1930.52,2315.53 2993.27,2315.53 3057.23,2251.57 v1(3057.23,1147.69) ; v1(2156.08,816.43) 2559.34,816.43 v1(2799.82,1056.91)
  Bottom Layer w5.8: v1(845.85,1904.1) 845.42,1904.1 797.14,1855.82 797.14,1648.45 742.65,1593.97 742.65,1532.48 773.89,1501.24 831.32,1501.24 831.37,1501.18 843.11,1501.18 856.4,1487.89 865.1,1487.89 v1@868.23,1484.75
SoC_CLKIN: U1.T1 U7.4 | length 209.4
  Top Layer w5.8: U7.4@639.57,974.72 642.09,977.25 642.09,996.36 720.46,1074.73 728.96,1083.23 737.7,1091.97 U1.T1@789.16,1091.97
SoC_CLKIN_BUF: R52.2 U7.2 | length 382.2
  Top Layer w5.8: R52.2@430.18,629.77 455.17,629.77 477.33,651.94 537.14,651.94 607.23,722.03 607.23,852.18 613.98,858.93 U7.2@613.98,886.14
SOP0: R223.2 U17.13 | length 1740.5
  Top Layer w5.8: v1(76.84,1363.32) 163.76,1363.32 246.08,1445.64 323.64,1445.64 383.81,1385.47 383.81,1301.01 352.91,1270.12 R223.2@352.91,1255
  L03_SIG1 w3.6: v1(76.84,1363.32) 139.84,1363.32 154.42,1377.91 154.42,1509.59 75.66,1588.35 75.66,1768.61 102.31,1795.25 102.31,2051.53 220.53,2169.75 v1(220.53,2196.86)
  Bottom Layer w5.8: v1(220.53,2196.86) 220.53,2238.57 277.14,2295.18 U17.13@391.42,2295.18
SOP1: R224.2 U17.12 | length 2280.4
  L03_SIG1 w3.6: v1(103.34,882.33) 103.34,908.66 79,933 79,1275 63,1291 63,1325.76 81.24,1343.99 134.09,1343.99 164.02,1373.93 164.02,1519.41 88.04,1595.39 88.04,1737.38 113.1,1762.44 113.1,2047.05 257.81,2191.76 v1(257.81,2229.62)
  L08_SIG2 w3.6: v1(103.34,882.33) 113.99,892.98 221.45,892.98 273.29,841.15 288.34,841.15 353.61,906.42 379.72,906.42 448.48,837.67 521.13,837.67 v1(551.1,867.64)
  Bottom Layer w5.8: v1(257.81,2229.62) 257.81,2245.64 291.6,2279.43 U17.12@391.42,2279.43 ; R224.2@543.37,901 543.37,877.14 551.1,869.41 v1(551.1,867.64)
SOP2: R225.2 U17.11 | length 1097.4
  Top Layer w5.8: v1(647.36,2007.41) 681.63,1973.14 910.57,1973.14 987.02,1896.69 1045.06,1896.69 1082.91,1934.53 1126.84,1934.53 1149.53,1911.85 1149.53,1841.95 1136.94,1829.35 R225.2@1136.94,1804.88
  Bottom Layer w5.8: U17.11@391.42,2263.68 476.38,2263.68 647.36,2092.71 v1(647.36,2007.41)
SOP3: R226.2 U17.10 | length 1132.5
  Top Layer w5.8: v1(632.08,1984.22) 656.16,1960.14 905.19,1960.14 991.11,1874.21 v1(991.11,1873.18)
  Bottom Layer w5.8: U17.10@391.42,2247.94 472.12,2247.94 603.42,2116.64 603.42,2012.88 v1(632.08,1984.22) ; v1(991.11,1873.18) 991.11,1727.08 1047.92,1670.27 1104.67,1670.27 1114.68,1660.26 R226.2@1114.68,1641.45
SPI0/FSITX0_MUX_SEL: R302.1 U12.7 U13.1 | length 1783.1
  Top Layer w5.8: v1(458.23,1848.01) 476.13,1848.01 488.48,1835.65 U12.7@514.43,1835.65
  L08_SIG2 w3.6: v1(769.42,2298.54) 830.43,2298.54 881.09,2247.88 1012.83,2247.88 1038.36,2273.41 1278.24,2273.41 1306.02,2301.19 1409.01,2301.19 1421.11,2289.09 1467.2,2289.09 1526.72,2348.61 v1(1646.82,2348.61)
  Bottom Layer w5.8: v1(458.23,1848.01) 482.13,1848.01 520.94,1886.81 634.07,1886.81 727.08,1979.82 727.08,2226.39 769.42,2268.73 v1(769.42,2298.54) ; v1(1646.82,2348.61) 1663.37,2365.16 R302.1@1681.01,2365.16 1681.01,2346.45 1687.43,2340.02 U13.1@1730.57,2340.02
SPI0_MUX_OE#: R303.1 U13.15 | length 100.8
  Bottom Layer w5.8: U13.15@1506.16,2314.43 1542.92,2314.43 1578.39,2349.91 R303.1@1578.39,2363.8
SPI1_MUX_OE#: R259.1 U24.15 | length 134.1
  Top Layer w5.8: R259.1@1801.56,2074.93 1819.84,2074.93 1826.45,2068.31 1826.45,2035.54 1834.35,2027.65 U24.15@1896.89,2027.65
SPI3_MUX_OE#: R309.1 U18.15 | length 103
  Bottom Layer w5.8: R309.1@1207.13,2151.47 1207.13,2216.83 1214.55,2224.24 U18.15@1241.71,2224.24
SPI3_MUX_SEL: R305.2 U12.8 U18.1 | length 1048.5
  Top Layer w5.8: U12.8@514.43,1815.97 475.34,1815.97 467.41,1808.04 467.41,1766.42 490.91,1742.92 556.39,1742.92 567.69,1731.62 648.16,1731.62 656.72,1740.17 656.72,1740.28 668.36,1751.92 668.36,1768.14 711.18,1810.97 711.18,1887.54 729.77,1906.13 806.18,1906.13 826.11,1886.2 870.93,1886.2 879.57,1894.83 884.37,1894.83 884.79,1894.42 898.18,1894.42 v1(900.51,1892.09)
  Bottom Layer w5.8: v1(900.51,1892.09) 900.51,1892.91 928.67,1921.07 928.67,1982.67 986.64,2040.64 R305.2@986.64,2168.12 986.64,2192.59 991.21,2197.16 1015.81,2197.16 U18.1@1017.3,2198.65
SW_PB_INTn: SW3.2 U23.3 | length 311.5
  Top Layer w5.8: SW3.2@1284.9,2378.25 1284.9,2412.92 1296.76,2424.78 1374.72,2424.78 1392.04,2407.46 v1(1392.68,2407.46)
  Bottom Layer w5.8: U23.3@1363.85,2262.41 1363.85,2283.57 1392.68,2312.4 v1(1392.68,2407.46)
SW_PB_PORz: SW2.2 U23.1 | length 513.1
  Top Layer w5.8: SW2.2@1002.73,2378.25 v1(1002.73,2423.47)
  Bottom Layer w5.8: v1(1002.73,2423.47) 1034.14,2423.47 1045.07,2434.41 1272.59,2434.41 1297.91,2409.09 1297.91,2310.72 1324.48,2284.16 U23.1@1324.48,2262.41
SW_PB_RESETz: SW4.2 U23.6 | length 475.8
  Top Layer w5.8: v1(1375.21,2171.84) 1538.51,2171.84 1587.03,2123.32 1724.59,2123.32 1744.23,2103.67 SW4.2@1744.23,2065.26
  Bottom Layer w5.8: U23.6@1363.85,2136.43 1363.85,2160.47 v1(1375.21,2171.84)
SW_SOP0: R230.2 SW1.1 U17.4 | length 186.7
  Top Layer w5.8: v1(545.38,2348.37) 545.13,2348.63 545.13,2369.28 R230.2@544.87,2369.54 SW1.1@594.87,2369.54
  Bottom Layer w5.8: v1(545.38,2348.37) 545.38,2322.88 573.09,2295.18 U17.4@623.7,2295.18
SW_SOP1: R229.2 SW1.2 U17.5 | length 207.9
  Top Layer w5.8: R229.2@545.86,2319.54 SW1.2@594.87,2319.54 647.58,2319.54 v1(680.41,2286.71)
  Bottom Layer w5.8: U17.5@623.7,2279.43 657.26,2279.43 664.53,2286.71 v1(680.41,2286.71)
SW_SOP2: R228.2 SW1.3 U17.6 | length 187.5
  Top Layer w5.8: R228.2@544.87,2269.54 SW1.3@594.87,2269.54 656.88,2269.54 v1(672.68,2253.73)
  Bottom Layer w5.8: U17.6@623.7,2263.68 624.1,2263.29 663.13,2263.29 v1(672.68,2253.73)
SW_SOP3: R227.2 SW1.4 U17.7 | length 359.8
  Top Layer w5.8: SW1.4@594.87,2219.54 625.73,2219.54 633.33,2211.94 633.33,2198.79 624.35,2189.81 608.6,2189.81 594.92,2176.13 594.92,2161.27 609.15,2147.04 R227.2@644.79,2147.04 673.91,2147.04 685.81,2158.94 v1(685.81,2230.17)
  Bottom Layer w5.8: U17.7@623.7,2247.94 624.1,2247.54 653.56,2247.54 670.65,2230.45 685.53,2230.45 v1(685.81,2230.17)
TCK: J5.3 R61.2 R65.1 | length 510.6
  Top Layer w5.8: J5.3@2362.59,1769.47 2413.59,1769.47 2429.14,1785.02 2429.14,1879.92 2522.8,1973.58 2617.09,1973.58 v1(2631.66,1959.01) 2634.96,1959.01 2645.5,1948.47 2654.53,1948.47 2660.84,1942.16 R65.1@2660.84,1923.29
  Bottom Layer w5.8: v1(2631.66,1959.01) 2631.92,1959.27 2653.8,1959.27 2657.2,1955.87 R61.2@2657.2,1942.55
TDI: J5.5 R63.2 | length 510.6
  Top Layer w5.8: J5.5@2362.59,1749.78 2416.95,1749.78 2444.87,1777.71 2444.87,1877.26 2525.51,1957.9 2600.42,1957.9 2635.01,1923.31 2635.01,1893.61 2641.18,1887.44 v1@2656.67,1887.44
  Bottom Layer w5.8: v1(2656.9,1887.67) R63.2@2682.31,1887.67
TDO: J5.4 R62.2 | length 268.8
  Top Layer w5.8: J5.4@2588.18,1769.47 2641.57,1769.47 2650.93,1760.11 2748.81,1760.11 2763.02,1745.89 2804.28,1745.89 2822.71,1764.32 R62.2@2839.62,1764.32
TEMP_CAL: R166.2 U1.U1 | length 115.9
  Top Layer w5.8: R166.2@705.02,1004.78 705.02,1019.58 720.46,1035.01 745.92,1060.47 U1.U1@789.16,1060.47
TMS: J5.2 R60.2 | length 95.7
  Top Layer w5.8: J5.2@2588.5,1788.84 2642.98,1788.84 2658.07,1803.93 R60.2@2677.96,1803.93
USER_LED0: D2.1 R215.1 | length 981.6
  Top Layer w5.6: D2.1@1525.61,806.89 1538.06,819.33 v1(1554.83,819.33)
  L08_SIG2 w3.6: v1(1106.54,523.15) 1106.54,566.54 1123.91,583.91 1212.79,583.91 1253.29,543.4 1327.73,543.4 1382.62,598.29 1499.63,598.29 1510.65,587.27 1591.27,587.27 1642.25,638.24 1642.25,805.38 1614.38,833.25 1584.9,833.25 1570.98,819.33 v1(1554.83,819.33)
  Bottom Layer w5.8: v1(1106.54,523.15) 1107.8,521.89 1107.8,501.56 R215.1@1109.06,500.3
USER_LED1: D3.1 R237.1 | length 1207.7
  Top Layer w5.8: v1(691.1,948.59) 669.02,948.59 659.6,939.18 659.6,821.92 660.05,821.47 660.05,791.77 647.44,779.16 647.44,761.51 683.81,725.14 774.6,725.14 817.36,682.38 v1(863.77,682.38) ; v1(1387.52,765.01) 1388.78,766.27 D3.1@1388.78,806.89
  L08_SIG2 w3.6: v1(863.77,682.38) 863.89,682.5 940.35,682.5 1050.59,792.74 1139.69,792.74 1168.17,821.22 1267.19,821.22 1298.21,790.2 1298.21,749.05 1306.55,740.71 1306.55,740.55 1318.02,729.07 1338.14,729.07 1374.08,765.01 v1(1387.52,765.01)
  Bottom Layer w5.8: v1@691.03,948.66 691.03,965.89 697.74,972.61 708.53,972.61 R237.1@709.71,971.43
VCC_1V2: C1.1 C2.1 C3.1 C4.1 C15.1 C16.1 C17.1 C18.1 C19.1 C20.1 C21.1 C22.1 C24.1 C25.1 C26.1 C27.1 C34.1 C35.1 C36.1 C37.1 C38.1 C39.1 C41.1 C42.1 C43.1 C55.1 R9.1 R11.1 R43.4 TP16.1 U1.D10 U1.E9 U1.E11 U1.F9 U1.F11 U1.G5 U1.G6 U1.G13 U1.G14 U1.H3 U1.J16 U1.K5 U1.K6 U1.K13 U1.K14 U1.N5 U1.N6 U1.N13 U1.N14 | length 631.3
  Top Layer w15: v1(837.09,1358.38) 851.39,1344.08 852.01,1344.08 U1.H3@852.16,1343.93 ; v1(899.4,1170.71) U1.N5@915.15,1186.45 ; v1(899.4,1265.19) U1.K5@915.15,1280.94 ; v1(899.4,1391.18) U1.G5@915.15,1375.43 ; v1(930.9,1170.71) U1.N6@946.64,1186.45 ; v1(930.9,1265.19) U1.K6@946.64,1280.94 ; v1(930.9,1391.18) U1.G6@946.64,1375.43 ; v1(1025.39,1422.67) U1.F9@1041.13,1406.93 ; v1(1025.39,1454.17) U1.E9@1041.13,1438.42 ; U1.D10@1072.63,1469.92 v1(1088.38,1485.67) ; U1.F11@1104.12,1406.93 v1(1119.87,1422.67) ; U1.E11@1104.12,1438.42 v1(1119.87,1454.17) ; U1.N13@1167.12,1186.45 v1(1182.86,1170.71) ; U1.K13@1167.12,1280.94 v1(1182.87,1265.19) ; U1.G13@1167.12,1375.43 v1(1182.87,1391.18) ; U1.N14@1198.61,1186.45 v1(1214.36,1170.71) ; U1.K14@1198.61,1280.94 v1(1214.36,1265.19) ; U1.G14@1198.61,1375.43 v1(1214.36,1391.18) ; U1.J16@1261.61,1312.44 v1(1277.35,1328.19)
  Top Layer w17: v1@1587.84,1556.72 1588.12,1556.72 1601.23,1569.83 1628.79,1569.83 R43.4@1629.26,1570.31
  Bottom Layer w10: C25.1@888.4,1175.71 888.4,1174.92 889.7,1173.62 894.32,1173.62 897.24,1170.71 v1(899.4,1170.71) ; v1(899.4,1391.18) 900.93,1392.71 907.48,1392.71 908.31,1393.54 909.1,1393.54 910.4,1394.84 C4.1@910.4,1395.63 ; C26.1@919.9,1175.71 919.9,1174.92 921.2,1173.62 921.98,1173.62 923.37,1172.24 929.37,1172.24 v1(930.9,1170.71) ; v1(930.9,1391.18) 933.06,1391.18 935.42,1393.54 940.6,1393.54 941.9,1394.84 C15.1@941.9,1395.63 ; C19.1@1114.87,1411.67 1115.66,1411.67 1116.96,1412.97 1116.96,1417.6 1119.87,1420.51 v1(1119.87,1422.67) ; v1(1119.87,1454.17) 1119.87,1452 1122.24,1449.64 1122.24,1444.47 1123.53,1443.17 C18.1@1124.32,1443.17 ; C27.1@1171.87,1175.71 1171.87,1174.92 1173.16,1173.62 1177.79,1173.62 1180.7,1170.71 v1(1182.86,1170.71) ; C20.1@1171.87,1396.18 1171.87,1395.39 1173.16,1394.09 1177.79,1394.09 1180.7,1391.18 v1(1182.87,1391.18) ; C35.1@1203.36,1175.71 1203.36,1174.92 1204.66,1173.62 1209.28,1173.62 1212.2,1170.71 v1(1214.36,1170.71) ; C21.1@1203.36,1396.18 1203.36,1395.39 1204.66,1394.09 1209.28,1394.09 1212.2,1391.18 v1(1214.36,1391.18)
  Bottom Layer w17: v1(1056.79,1202.2) 1056.79,1201.93 1057.21,1201.5 R9.1@1057.21,1174.67
  other v1: 1415.31,1308.68 1415.6,1327.29 734.92,1343.63 1536.86,1520.36 1558.71,1520.36 1583.21,1520.36 1536.86,1542.32 1558.71,1542.32 1583.21,1542.32 1536.86,1564.28 1558.71,1564.28 1583.21,1564.28 1061.51,1624.85 1063.43,1644.93
VCC_1V2_N: R43.1 R71.1 | length 2463.3
  Top Layer w3.2: R43.1@1672.57,1598.85 1672.57,1597.57 1678.81,1591.33 1679.19,1591.33 1683.34,1587.18 1715.83,1587.18 1718.79,1590.15 v1(1722.8,1590.15)
  Top Layer w4.25: v1(2686.3,1461.74) 2686.63,1461.74 2718.63,1493.74 2760.33,1493.74 2810.56,1543.97 2810.56,1564.51 2838.79,1592.74 2848.44,1592.74 2863.87,1608.17 2863.87,1672.55 2934.3,1742.98 2997.6,1742.98 3031.56,1709.03 3031.56,1661.69 3013.87,1644.01 v1(3013.87,1641.14)
  L08_SIG2 w3.2: v1(1722.8,1590.15) 1723.15,1590.5 1776.8,1590.5 1827.06,1540.24 1863.11,1540.24 1928.58,1474.77 2026.42,1474.77 2049.5,1497.85 2081.25,1497.85 2090.55,1488.55 2160.06,1488.55 2175.67,1504.16 2243.82,1504.16 2249.06,1509.4 2249.06,1585.07 2277.2,1613.21 2318.88,1613.21 2344.03,1588.07 2344.03,1586.85 2344.1,1586.79 2344.1,1492.9 2361.68,1475.31 2672.73,1475.31 v1(2686.3,1461.74)
  Bottom Layer w4.25: R71.1@2980.39,2096.29 2972.68,2088.58 2967.7,2088.58 2965.29,2086.16 2965.29,2039.34 2906.36,1980.42 2906.36,1925.23 3041.8,1789.79 3041.8,1652.55 3032.74,1643.49 3016.22,1643.49 v1(3013.87,1641.14)
VCC_1V2_P: R43.2 R67.1 | length 2401.8
  Top Layer w3.2: R43.2@1672.57,1570.31 1672.57,1571.58 1678.81,1577.83 1680.09,1577.83 1680.24,1577.98 1711.48,1577.98 1723.82,1565.64 v1(1727.76,1565.64)
  Top Layer w4.25: v1(2652.87,1453.01) 2653.09,1453.23 2668.43,1453.23 2678.21,1443.45 2692.56,1443.45 2712.56,1463.45 2712.56,1472.26 2722.59,1482.29 2763.37,1482.29 2821.59,1540.5 2821.59,1559.77 2843.11,1581.29 2852.15,1581.29 2874.12,1603.26 2874.12,1666.61 2939.04,1731.53 2992.86,1731.53 3013.49,1710.9 v1(3013.49,1667.85)
  L08_SIG2 w3.2: v1(1727.76,1565.64) 1730.59,1568.48 1739.88,1568.48 1739.96,1568.55 1743.16,1568.55 1758.54,1553.17 1775.94,1553.17 1785.15,1562.38 1790.86,1562.38 1823.7,1529.54 1859.11,1529.54 1924.27,1464.37 2025.86,1464.37 2049.56,1440.67 2082.1,1440.67 2088.37,1446.94 2122.79,1446.94 2142.31,1466.46 2220.49,1466.46 2258.26,1504.24 2258.26,1580.92 2279.86,1602.51 2316.57,1602.51 2333.33,1585.76 2333.33,1488.44 2354.88,1466.89 2357.1,1466.89 2357.87,1466.11 2639.95,1466.11 2652.87,1453.19 v1(2652.87,1453.01)
  Bottom Layer w4.25: R67.1@2938.78,2096.29 2946.5,2088.58 2951.47,2088.58 2953.89,2086.16 2953.89,2044.07 2894.96,1985.14 2894.96,1920.51 3030.4,1785.07 3030.4,1675.69 3025.19,1670.48 3016.12,1670.48 v1(3013.49,1667.85)
VCC_6V0: C73.1 C86.1 C87.2 C88.2 C89.2 C90.2 C91.1 C93.1 C169.1 TP8.1 U2.41 U2.42 U3.6 | length 47.6
  Top Layer w10: U3.6@1689.83,1818 1717.4,1818 1731.58,1832.17
  other v1: 1942.46,1315.87 1951.62,1331.69 1934.27,1336.29 1892.22,1384.98 1889.07,1402.7 1868.84,1490.02 1834.03,1556.84 1820.52,1787.06 1841.77,1796.2 1823.83,1808.95
VDD_IO_3V3: C5.1 C6.1 C7.1 C8.1 C9.1 C10.1 C11.1 C12.1 C13.1 C14.1 C28.1 C30.1 FB1.1 R44.4 TP17.1 U1.D8 U1.D12 U1.H4 U1.H15 U1.L15 U1.P4 U1.R15 | length 306.1
  Top Layer w10: v1(1564.43,1320.84) 1564.61,1320.67 1564.61,1291.06 TP17.1@1564.79,1290.88
  Top Layer w15: v1(867.9,1139.21) U1.P4@883.65,1154.96 ; v1(867.9,1359.68) U1.H4@883.65,1343.93 ; v1(993.89,1485.67) U1.D8@1009.64,1469.92 ; U1.D12@1135.62,1469.92 v1(1151.37,1485.67) ; U1.R15@1230.11,1123.46 v1(1245.86,1107.71) ; U1.L15@1230.11,1249.45 v1(1245.86,1233.7) ; U1.H15@1230.11,1343.93 v1(1245.86,1359.68)
  Bottom Layer w10: v1(867.9,1139.21) 867.91,1141.38 870.82,1144.29 870.82,1148.91 872.12,1150.21 C12.1@872.91,1150.21 ; v1(867.9,1359.68) 867.9,1361.85 870.82,1364.76 870.82,1369.38 872.12,1370.68 C8.1@872.91,1370.68 ; C13.1@985.44,1477.87 985.77,1477.87 993.56,1485.67 v1(993.89,1485.67) ; C30.1@990.84,947.78 992.14,946.48 1017.11,946.48 FB1.1@1019.7,943.89 ; C11.1@1236.32,1116.69 1236.6,1116.69 1245.58,1107.71 v1(1245.86,1107.71) ; C9.1@1241.41,1244.7 1242.2,1244.7 1243.49,1243.4 1243.49,1238.22 1245.86,1235.86 v1(1245.86,1233.7) ; C10.1@1241.41,1370.68 1242.2,1370.68 1243.49,1369.38 1243.49,1364.21 1245.86,1361.85 v1(1245.86,1359.68)
  Bottom Layer w12: v1@1151.37,1485.02 C14.1@1159.16,1477.22
  other v1: 992.86,904.56 996.04,926.32 1564.26,1355.36 1574.95,1400.17 2028.9,1662.25 2028.66,1680.42 2028.41,1698.24
VDD_IO_3V3_N: R44.1 R70.1 | length 2432.9
  Top Layer w4.25: v1(229.7,2069.41) 226.11,2069.41 219.72,2063.01 219.57,2063.01 219.52,2062.96 216.02,2062.96 208.25,2070.74 208.25,2124.94 326.99,2243.68 445.53,2243.68 680.16,2009.06 891.94,2009.06 953.77,1947.23 1145.79,1947.23 1203.31,1889.71 1318.55,1889.71 1343.28,1914.44 1422.27,1914.44 1477.7,1969.87 1538.2,1969.87 1547.52,1960.54 1604.72,1960.54 1640.47,1996.29 1685.19,1996.29 1751.7,1929.78 1775.97,1929.78 1782.11,1935.93 1791.9,1935.93 1805.42,1922.41 1805.42,1910.06 1801.45,1906.09 1797.52,1906.09 v1(1787.38,1916.23)
  Bottom Layer w4.25: R70.1@197.35,2081.01 197.35,2063.92 199.84,2061.43 220.33,2061.43 228.31,2069.41 v1(229.7,2069.41) ; v1(1787.38,1916.23) 1797.16,1906.45 1838.77,1906.45 1995.17,1750.04 2059.34,1750.04 2068.5,1740.88 2068.5,1725.35 2075.6,1718.25 R44.1@2077.07,1718.25
VDD_IO_3V3_P: R44.2 R66.1 | length 2475.5
  Top Layer w4.25: v1(227.76,2039.66) 224.04,2039.66 219.86,2043.84 218.95,2043.84 196.8,2065.99 196.8,2129.68 322.25,2255.13 450.28,2255.13 684.9,2020.51 896.68,2020.51 958.51,1958.68 1150.53,1958.68 1208.05,1901.16 1313.81,1901.16 1338.54,1925.89 1417.53,1925.89 1471.76,1980.12 1544.14,1980.12 1553.46,1970.79 1600.48,1970.79 1636.22,2006.54 1689.44,2006.54 1754.05,1941.92 1772.42,1941.92 1776.68,1946.18 1797.84,1946.18 1816.87,1927.15 1816.87,1905.31 1806.2,1894.64 1798.67,1894.64 1788.58,1884.55 v1(1787.38,1884.55)
  Bottom Layer w4.25: R66.1@197.35,2039.56 197.35,2041.53 207.01,2051.18 216.24,2051.18 v1(227.76,2039.66) ; v1(1787.38,1884.55) 1787.38,1884.91 1797.52,1895.05 1834.04,1895.05 1990.45,1738.64 2054.62,1738.64 2057.1,1736.16 2057.1,1725.35 2050.01,1718.25 R44.2@2048.53,1718.25
VDDA18_LDO_1V8: C49.1 C50.1 C51.1 C52.1 C54.1 FB2.1 R10.2 S2.1 U1.R6 U1.R8 U1.R11 | length 310.2
  Top Layer w15: v1(930.9,1107.71) U1.R6@946.64,1123.46 ; v1(993.89,1107.71) U1.R8@1009.64,1123.46 ; U1.R11@1104.12,1123.46 v1(1119.87,1107.71)
  Top Layer w20: v1(1479.32,766.15) 1479.32,675.3 1479.53,675.08 1479.53,666.41 1503.93,642.02 1504.18,642.02 1511.21,634.99 S2.1@1511.21,595.52
  L06_PWR2 w18: v1(993.89,1107.71) 1001.34,1100.27 ; 1112.33,1100.26 1112.42,1100.26 v1(1119.87,1107.71)
  Bottom Layer w10: C52.1@919.9,1112.71 919.9,1111.93 921.2,1110.63 921.98,1110.63 923.37,1109.25 929.37,1109.25 v1(930.9,1107.71) ; C51.1@982.89,1112.71 982.89,1111.93 984.19,1110.63 988.81,1110.63 991.72,1107.71 v1(993.89,1107.71) ; C50.1@1111.76,1115.18 1112.09,1115.18 1119.55,1107.71 v1(1119.87,1107.71)
  other v1: 648.42,1068.59
VDDA18_OSC_PLL_AM26x: C53.1 FB2.2 U1.R4 | length 68.4
  Top Layer w15: v1(867.91,1107.72) U1.R4@883.65,1123.46
  Bottom Layer w10: v1(867.91,1107.72) 867.91,1109.88 870.36,1112.34 870.36,1116.93 871.66,1118.22 C53.1@872.45,1118.22
  Bottom Layer w20: v1(700.12,1120.3) 709.34,1111.09 709.34,1094.76 FB2.2@712.13,1091.97
VDDA_3V3: C29.1 C31.1 C32.1 C33.1 C122.2 C152.1 FB1.2 U1.P7 U1.P9 U1.P11 U11.4 U20.8@709.14,645.23 | length 314.2
  Top Layer w10: C152.1@664.85,645.23 U20.8@709.14,645.23 ; C152.1@664.88,645.26 v1(664.91,668.73)
  Top Layer w15: v1(962.39,1139.21) U1.P7@978.14,1154.96 ; v1(1025.39,1139.21) U1.P9@1041.13,1154.96 ; U1.P11@1104.12,1154.96 v1(1119.87,1139.21) ; C122.2@1435.15,649.81 1435.15,614.32 1443.94,605.53 1456.36,605.53 v1(1467.52,616.69)
  Bottom Layer w10: C32.1@951.39,1144.21 951.39,1143.42 952.69,1142.12 953.48,1142.12 954.86,1140.74 960.86,1140.74 v1(962.39,1139.21) ; C33.1@1014.39,1144.21 1014.39,1143.42 1015.68,1142.12 1020.31,1142.12 1023.22,1139.21 v1(1025.39,1139.21) ; v1(1119.87,1139.21) 1119.87,1140.02 1124.87,1145.02 C31.1@1124.87,1150.21
  Bottom Layer w15: U11.4@1406.88,610.18 1460.21,610.18 1466.71,616.69 v1(1467.52,616.69)
  other v1: 1096.84,969.64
